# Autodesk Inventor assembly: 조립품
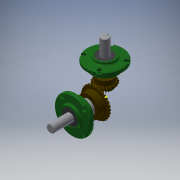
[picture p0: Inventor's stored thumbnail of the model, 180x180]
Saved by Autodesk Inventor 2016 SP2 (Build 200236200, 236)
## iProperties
Created: 2018-08
Part Number: 조립품
Document SubType Name: Assembly
Designer: Administrator
Author: Administrator
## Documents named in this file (13)
- Z:\ATC마스터자격증시험\480807V1027 이상규(인벤터)\조립품.iam
- Z:\ATC마스터자격증시험\480807V1027 이상규(인벤터)\본체.ipt
- Z:\ATC마스터자격증시험\480807V1027 이상규(인벤터)\메인 베벨기어.ipt
- Z:\ATC마스터자격증시험\480807V1027 이상규(인벤터)\메인 축.ipt
- 메인 축.ipt
- Z:\ATC마스터자격증시험\480807V1027 이상규(인벤터)\베어링 6203.ipt
- Z:\ATC마스터자격증시험\480807V1027 이상규(인벤터)\오일실 17 32 8.ipt
- Z:\ATC마스터자격증시험\480807V1027 이상규(인벤터)\커버.ipt
- Z:\ATC마스터자격증시험\480807V1027 이상규(인벤터)\키 5x5.ipt
- Z:\ATC마스터자격증시험\480807V1027 이상규(인벤터)\서브 베벨기어.ipt
- Z:\ATC마스터자격증시험\480807V1027 이상규(인벤터)\서브 축.ipt
- 서브 축.ipt
- Z:\ATC마스터자격증시험\480807V1027 이상규(인벤터)\키 4x4.ipt
